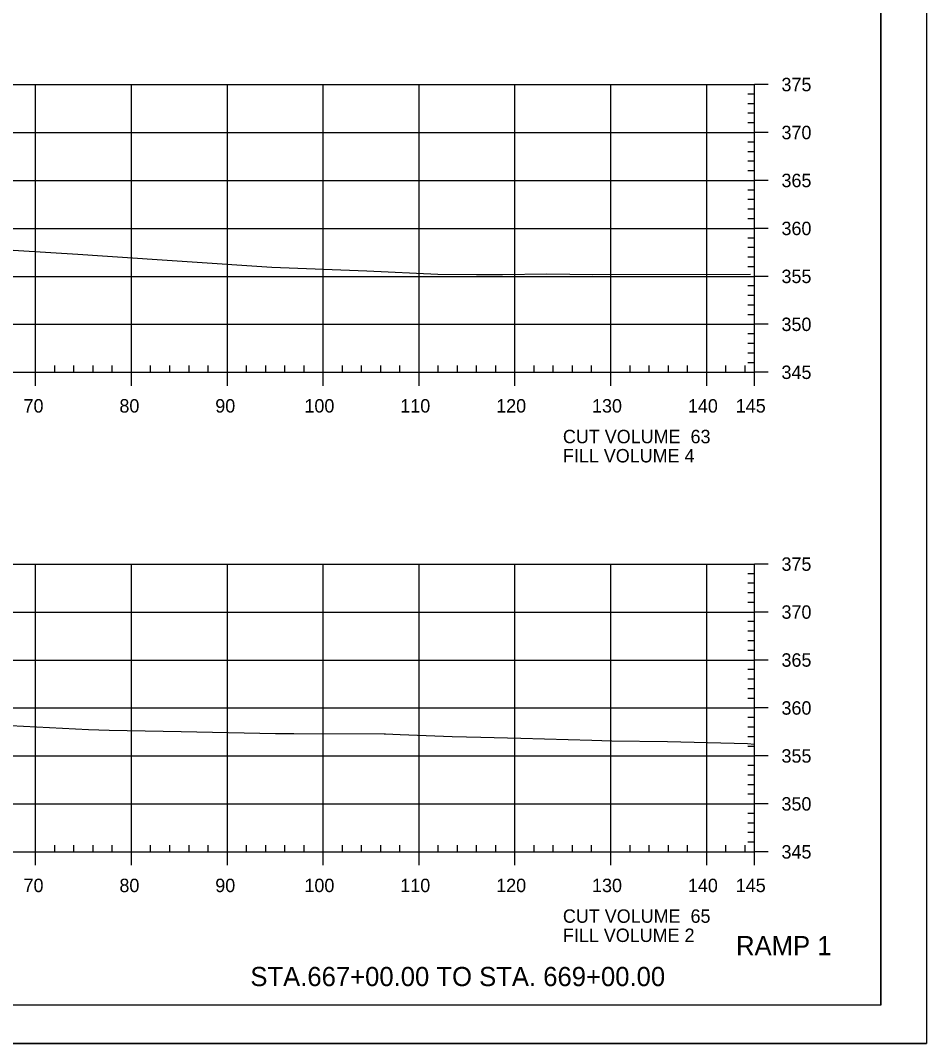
# Model space of a CAD drawing. Extents: x 1359801 to 1362404, y 372415 to 374228.
# Drawn here: x 1360039.8 to 1360134.3, y 373588 to 373694.6 of the extents above; entities that cross this region are included whole.
import ezdxf

# ---------------------------------------------------------------- set-up
doc = ezdxf.new("R2010")
doc.units = 0
for name, color, linetype in [('S_DRG_PT_SYM', 7, 'Continuous'), ('S_MAILBOX', 7, 'Continuous'), ('S_PRIMARY_CTL', 7, 'Continuous'), ('S_SHOULDER', 7, 'Continuous'), ('S_SIGN', 7, 'Continuous'), ('S_UTL_PT_SYM', 7, 'Continuous'), ('S_WATER_UTILITIES', 7, 'Continuous')]:
    doc.layers.add(name, color=color, linetype=linetype)

msp = doc.modelspace()

# ---------------------------------------------------------------- linework, layer by layer
at = {"layer": 'S_DRG_PT_SYM'}
for points in [[(1360029.96, 373671.24), (1360045.75, 373670.25), (1360048.34, 373670.09), (1360065.98, 373668.9), (1360075.9, 373668.53), (1360083.31, 373668.16), (1360087.34, 373668.12), (1360090.05, 373668.15), (1360094.67, 373668.19), (1360099.49, 373668.14), (1360115.93, 373668.17)], [(1360035.98, 373621.24), (1360046.87, 373620.68), (1360049.02, 373620.63), (1360056.52, 373620.47), (1360066.37, 373620.29), (1360068.3, 373620.28), (1360077.72, 373620.26), (1360077.84, 373620.25), (1360079.36, 373620.19), (1360084.8, 373619.98), (1360087.78, 373619.9), (1360091.97, 373619.8), (1360099.36, 373619.59), (1360101.47, 373619.53), (1360107.26, 373619.46), (1360115.61, 373619.22), (1360116.35, 373619.18)]]:
    msp.add_lwpolyline(points, dxfattribs=at)
at = {"layer": 'S_MAILBOX'}
for p, q in [((1359826.35, 373687.94), (1360116.35, 373687.94)), ((1360041.35, 373657.94), (1360041.35, 373687.94)), ((1360051.35, 373657.94), (1360051.35, 373687.94)), ((1360061.35, 373657.94), (1360061.35, 373687.94)), ((1360071.35, 373657.94), (1360071.35, 373687.94)), ((1360081.35, 373657.94), (1360081.35, 373687.94)), ((1360091.35, 373657.94), (1360091.35, 373687.94)), ((1360101.35, 373657.94), (1360101.35, 373687.94)), ((1360111.35, 373657.94), (1360111.35, 373687.94)), ((1360116.35, 373657.94), (1360116.35, 373687.94)), ((1359826.35, 373682.94), (1360116.35, 373682.94)), ((1359826.35, 373677.94), (1360116.35, 373677.94)), ((1359826.35, 373672.94), (1360116.35, 373672.94)), ((1359826.35, 373667.94), (1360116.35, 373667.94)), ((1359826.35, 373662.94), (1360116.35, 373662.94)), ((1359826.35, 373657.94), (1360116.35, 373657.94)), ((1359826.35, 373637.94), (1360116.35, 373637.94)), ((1360041.35, 373607.94), (1360041.35, 373637.94)), ((1360051.35, 373607.94), (1360051.35, 373637.94)), ((1360061.35, 373607.94), (1360061.35, 373637.94)), ((1360071.35, 373607.94), (1360071.35, 373637.94)), ((1360081.35, 373607.94), (1360081.35, 373637.94)), ((1360091.35, 373607.94), (1360091.35, 373637.94)), ((1360101.35, 373607.94), (1360101.35, 373637.94)), ((1360111.35, 373607.94), (1360111.35, 373637.94)), ((1360116.35, 373607.94), (1360116.35, 373637.94)), ((1359826.35, 373632.94), (1360116.35, 373632.94)), ((1359826.35, 373627.94), (1360116.35, 373627.94)), ((1359826.35, 373622.94), (1360116.35, 373622.94)), ((1359826.35, 373617.94), (1360116.35, 373617.94)), ((1359826.35, 373612.94), (1360116.35, 373612.94)), ((1359826.35, 373607.94), (1360116.35, 373607.94))]:
    msp.add_line(p, q, dxfattribs=at)
at = {"layer": 'S_SHOULDER'}
msp.add_line((1359800.95, 373587.96), (1360134.28, 373587.96), dxfattribs=at)
for points in [[(1359800.94, 373801.29), (1360134.28, 373801.29), (1360134.28, 373587.95), (1359800.94, 373587.95)], [(1360047.27, 373797.4), (1360047.27, 373787.52), (1360083, 373787.52), (1360083, 373784.6), (1360106.2, 373784.6), (1360106.2, 373760.26), (1360129.53, 373760.26), (1360129.53, 373591.94), (1359813.35, 373591.94), (1359813.35, 373797.4)]]:
    msp.add_lwpolyline(points, close=True, dxfattribs=at)
at = {"layer": 'S_UTL_PT_SYM'}
for q in [(1360129.53, 373797.4), (1359813.35, 373591.94)]:
    msp.add_line((1360129.53, 373591.94), q, dxfattribs=at)
at = {"layer": 'S_WATER_UTILITIES'}
for p, q in [((1360116.35, 373657.94), (1360116.35, 373687.94)), ((1360117.75, 373687.94), (1360116.35, 373687.94)), ((1360116.35, 373686.94), (1360115.65, 373686.94)), ((1360116.35, 373685.94), (1360115.65, 373685.94)), ((1360116.35, 373684.94), (1360115.65, 373684.94)), ((1360116.35, 373683.94), (1360115.65, 373683.94)), ((1360117.75, 373682.94), (1360116.35, 373682.94)), ((1360116.35, 373681.94), (1360115.65, 373681.94)), ((1360116.35, 373680.94), (1360115.65, 373680.94)), ((1360116.35, 373679.94), (1360115.65, 373679.94)), ((1360116.35, 373678.94), (1360115.65, 373678.94)), ((1360117.75, 373677.94), (1360116.35, 373677.94)), ((1360116.35, 373676.94), (1360115.65, 373676.94)), ((1360116.35, 373675.94), (1360115.65, 373675.94)), ((1360116.35, 373674.94), (1360115.65, 373674.94)), ((1360116.35, 373673.94), (1360115.65, 373673.94)), ((1360117.75, 373672.94), (1360116.35, 373672.94)), ((1360116.35, 373671.94), (1360115.65, 373671.94)), ((1360116.35, 373670.94), (1360115.65, 373670.94)), ((1360116.35, 373669.94), (1360115.65, 373669.94)), ((1360116.35, 373668.94), (1360115.65, 373668.94)), ((1360117.75, 373667.94), (1360116.35, 373667.94)), ((1360116.35, 373666.94), (1360115.65, 373666.94)), ((1360116.35, 373665.94), (1360115.65, 373665.94)), ((1360116.35, 373664.94), (1360115.65, 373664.94)), ((1360116.35, 373663.94), (1360115.65, 373663.94)), ((1360116.35, 373661.94), (1360115.65, 373661.94)), ((1360117.75, 373662.94), (1360116.35, 373662.94)), ((1360116.35, 373660.94), (1360115.65, 373660.94)), ((1360116.35, 373659.94), (1360115.65, 373659.94)), ((1360116.35, 373658.94), (1360115.65, 373658.94)), ((1359826.35, 373657.94), (1360116.35, 373657.94)), ((1360041.35, 373656.54), (1360041.35, 373657.94)), ((1360043.35, 373657.94), (1360043.35, 373658.64)), ((1360045.35, 373657.94), (1360045.35, 373658.64)), ((1360047.35, 373657.94), (1360047.35, 373658.64)), ((1360049.35, 373657.94), (1360049.35, 373658.64)), ((1360051.35, 373656.54), (1360051.35, 373657.94)), ((1360053.35, 373657.94), (1360053.35, 373658.64)), ((1360055.35, 373657.94), (1360055.35, 373658.64)), ((1360057.35, 373657.94), (1360057.35, 373658.64)), ((1360059.35, 373657.94), (1360059.35, 373658.64)), ((1360061.35, 373656.54), (1360061.35, 373657.94)), ((1360063.35, 373657.94), (1360063.35, 373658.64)), ((1360065.35, 373657.94), (1360065.35, 373658.64)), ((1360067.35, 373657.94), (1360067.35, 373658.64)), ((1360069.35, 373657.94), (1360069.35, 373658.64)), ((1360071.35, 373656.54), (1360071.35, 373657.94)), ((1360073.35, 373657.94), (1360073.35, 373658.64)), ((1360075.35, 373657.94), (1360075.35, 373658.64)), ((1360077.35, 373657.94), (1360077.35, 373658.64)), ((1360079.35, 373657.94), (1360079.35, 373658.64)), ((1360081.35, 373656.54), (1360081.35, 373657.94)), ((1360083.35, 373657.94), (1360083.35, 373658.64)), ((1360085.35, 373657.94), (1360085.35, 373658.64)), ((1360087.35, 373657.94), (1360087.35, 373658.64)), ((1360089.35, 373657.94), (1360089.35, 373658.64)), ((1360091.35, 373656.54), (1360091.35, 373657.94)), ((1360093.35, 373657.94), (1360093.35, 373658.64)), ((1360095.35, 373657.94), (1360095.35, 373658.64)), ((1360097.35, 373657.94), (1360097.35, 373658.64)), ((1360099.35, 373657.94), (1360099.35, 373658.64)), ((1360101.35, 373656.54), (1360101.35, 373657.94)), ((1360103.35, 373657.94), (1360103.35, 373658.64)), ((1360105.35, 373657.94), (1360105.35, 373658.64)), ((1360107.35, 373657.94), (1360107.35, 373658.64)), ((1360109.35, 373657.94), (1360109.35, 373658.64)), ((1360111.35, 373656.54), (1360111.35, 373657.94)), ((1360113.35, 373657.94), (1360113.35, 373658.64)), ((1360115.35, 373657.94), (1360115.35, 373658.64)), ((1360116.35, 373656.54), (1360116.35, 373657.94)), ((1360117.75, 373657.94), (1360116.35, 373657.94)), ((1360116.35, 373607.94), (1360116.35, 373637.94)), ((1360117.75, 373637.94), (1360116.35, 373637.94)), ((1360116.35, 373636.94), (1360115.65, 373636.94)), ((1360116.35, 373635.94), (1360115.65, 373635.94)), ((1360116.35, 373634.94), (1360115.65, 373634.94)), ((1360116.35, 373633.94), (1360115.65, 373633.94)), ((1360117.75, 373632.94), (1360116.35, 373632.94)), ((1360116.35, 373631.94), (1360115.65, 373631.94)), ((1360116.35, 373630.94), (1360115.65, 373630.94)), ((1360116.35, 373629.94), (1360115.65, 373629.94)), ((1360116.35, 373628.94), (1360115.65, 373628.94)), ((1360117.75, 373627.94), (1360116.35, 373627.94)), ((1360116.35, 373626.94), (1360115.65, 373626.94)), ((1360116.35, 373625.94), (1360115.65, 373625.94)), ((1360116.35, 373624.94), (1360115.65, 373624.94)), ((1360116.35, 373623.94), (1360115.65, 373623.94)), ((1360117.75, 373622.94), (1360116.35, 373622.94)), ((1360116.35, 373621.94), (1360115.65, 373621.94)), ((1360116.35, 373620.94), (1360115.65, 373620.94)), ((1360116.35, 373619.94), (1360115.65, 373619.94)), ((1360116.35, 373618.94), (1360115.65, 373618.94)), ((1360117.75, 373617.94), (1360116.35, 373617.94)), ((1360116.35, 373616.94), (1360115.65, 373616.94)), ((1360116.35, 373615.94), (1360115.65, 373615.94)), ((1360116.35, 373614.94), (1360115.65, 373614.94)), ((1360116.35, 373613.94), (1360115.65, 373613.94)), ((1360117.75, 373612.94), (1360116.35, 373612.94)), ((1360116.35, 373611.94), (1360115.65, 373611.94)), ((1360116.35, 373610.94), (1360115.65, 373610.94)), ((1360116.35, 373609.94), (1360115.65, 373609.94)), ((1360043.35, 373607.94), (1360043.35, 373608.64)), ((1360045.35, 373607.94), (1360045.35, 373608.64)), ((1360047.35, 373607.94), (1360047.35, 373608.64)), ((1360049.35, 373607.94), (1360049.35, 373608.64)), ((1360053.35, 373607.94), (1360053.35, 373608.64)), ((1360055.35, 373607.94), (1360055.35, 373608.64)), ((1360057.35, 373607.94), (1360057.35, 373608.64)), ((1360059.35, 373607.94), (1360059.35, 373608.64)), ((1360063.35, 373607.94), (1360063.35, 373608.64)), ((1360065.35, 373607.94), (1360065.35, 373608.64)), ((1360067.35, 373607.94), (1360067.35, 373608.64)), ((1360069.35, 373607.94), (1360069.35, 373608.64)), ((1360073.35, 373607.94), (1360073.35, 373608.64)), ((1360075.35, 373607.94), (1360075.35, 373608.64)), ((1360077.35, 373607.94), (1360077.35, 373608.64)), ((1360079.35, 373607.94), (1360079.35, 373608.64)), ((1360083.35, 373607.94), (1360083.35, 373608.64)), ((1360085.35, 373607.94), (1360085.35, 373608.64)), ((1360087.35, 373607.94), (1360087.35, 373608.64)), ((1360089.35, 373607.94), (1360089.35, 373608.64)), ((1360093.35, 373607.94), (1360093.35, 373608.64)), ((1360095.35, 373607.94), (1360095.35, 373608.64)), ((1360097.35, 373607.94), (1360097.35, 373608.64)), ((1360099.35, 373607.94), (1360099.35, 373608.64)), ((1360103.35, 373607.94), (1360103.35, 373608.64)), ((1360105.35, 373607.94), (1360105.35, 373608.64)), ((1360107.35, 373607.94), (1360107.35, 373608.64)), ((1360109.35, 373607.94), (1360109.35, 373608.64)), ((1360113.35, 373607.94), (1360113.35, 373608.64)), ((1360115.35, 373607.94), (1360115.35, 373608.64)), ((1360116.35, 373608.94), (1360115.65, 373608.94)), ((1359826.35, 373607.94), (1360116.35, 373607.94)), ((1360041.35, 373606.54), (1360041.35, 373607.94)), ((1360051.35, 373606.54), (1360051.35, 373607.94)), ((1360061.35, 373606.54), (1360061.35, 373607.94)), ((1360071.35, 373606.54), (1360071.35, 373607.94)), ((1360081.35, 373606.54), (1360081.35, 373607.94)), ((1360091.35, 373606.54), (1360091.35, 373607.94)), ((1360101.35, 373606.54), (1360101.35, 373607.94)), ((1360111.35, 373606.54), (1360111.35, 373607.94)), ((1360116.35, 373606.54), (1360116.35, 373607.94)), ((1360117.75, 373607.94), (1360116.35, 373607.94))]:
    msp.add_line(p, q, dxfattribs=at)

# ---------------------------------------------------------------- texts
at = {"layer": 'S_PRIMARY_CTL'}
for s, p in [('375', (1360119.15, 373687.24)), ('370', (1360119.15, 373682.24)), ('365', (1360119.15, 373677.24)), ('360', (1360119.15, 373672.24)), ('355', (1360119.15, 373667.24)), ('350', (1360119.15, 373662.24)), ('345', (1360119.15, 373657.24)), ('70', (1360040.09, 373653.74)), ('80', (1360050.09, 373653.74)), ('90', (1360060.09, 373653.74)), ('100', (1360069.39, 373653.74)), ('110', (1360079.39, 373653.74)), ('120', (1360089.39, 373653.74)), ('130', (1360099.39, 373653.74)), ('140', (1360109.39, 373653.74)), ('145', (1360114.38, 373653.74)), ('CUT VOLUME  63', (1360096.35, 373650.54)), ('FILL VOLUME 4', (1360096.35, 373648.54)), ('375', (1360119.15, 373637.24)), ('370', (1360119.15, 373632.24)), ('365', (1360119.15, 373627.24)), ('360', (1360119.15, 373622.24)), ('355', (1360119.15, 373617.24)), ('350', (1360119.15, 373612.24)), ('345', (1360119.15, 373607.24)), ('70', (1360040.09, 373603.74)), ('80', (1360050.09, 373603.74)), ('90', (1360060.09, 373603.74)), ('100', (1360069.39, 373603.74)), ('110', (1360079.39, 373603.74)), ('120', (1360089.39, 373603.74)), ('130', (1360099.39, 373603.74)), ('140', (1360109.39, 373603.74)), ('145', (1360114.38, 373603.74)), ('CUT VOLUME  65', (1360096.35, 373600.54)), ('FILL VOLUME 2', (1360096.35, 373598.54))]:
    msp.add_text(s, height=1.4, dxfattribs=at).set_placement(p)
at = {"layer": 'S_SIGN'}
for s, p in [('RAMP 1', (1360114.41, 373597.16)), ('STA.667+00.00 TO STA. 669+00.00', (1360063.75, 373593.94))]:
    msp.add_text(s, height=2, dxfattribs=at).set_placement(p)

doc.saveas('drawing.dxf')
